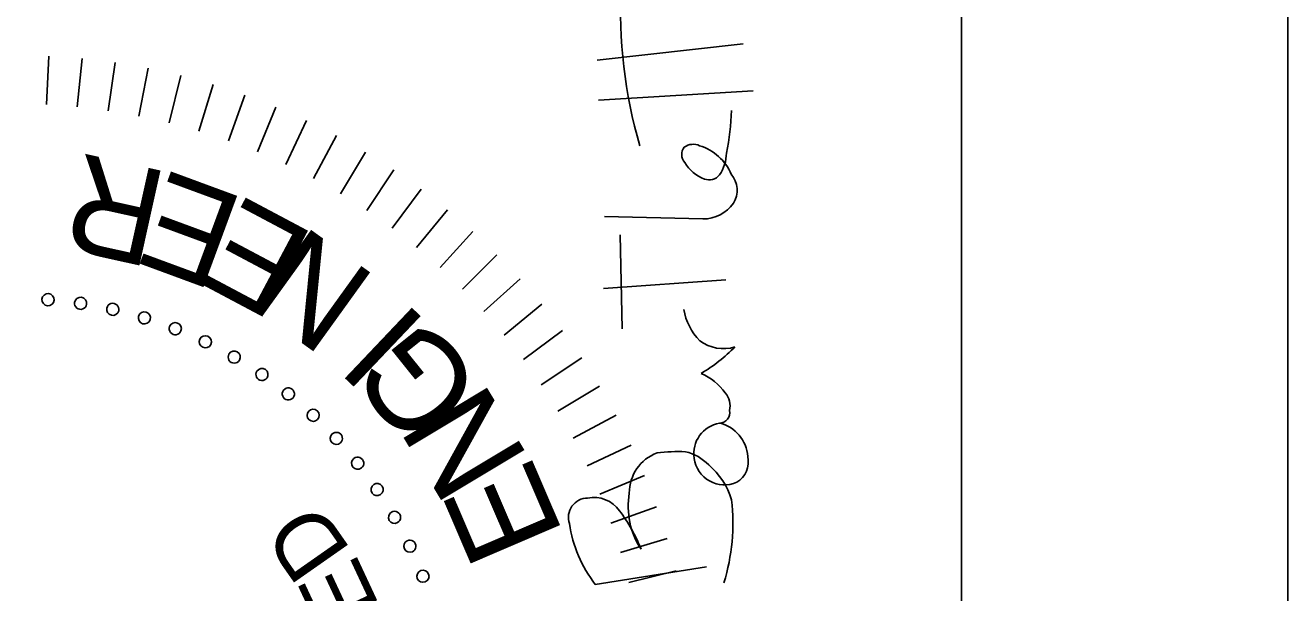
# Model space of a CAD drawing. Extents: x 916251 to 917164, y 328941 to 329491.
# Drawn here: x 917063.96 to 917100.87, y 329339.21 to 329355.8 of the extents above; entities that cross this region are included whole.
import ezdxf

# ---------------------------------------------------------------- set-up
doc = ezdxf.new("R2010")
doc.units = 0
for name, color, linetype in [('ANNOTATION', 7, 'Continuous'), ('Default', 7, 'Continuous'), ('elec-detail-ext-post-mtd-meter-panel', 7, 'Continuous')]:
    doc.layers.add(name, color=color, linetype=linetype)

# ---------------------------------------------------------------- blocks, each defined once
blk = doc.blocks.new('STAMP')
at = {"layer": 'Default'}
for p, q in [((0.007955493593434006, 0.0011091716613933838), (0.007387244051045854, 0.0011370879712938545)), ((0.007926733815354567, 0.0007192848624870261), (0.007360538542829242, 0.0007750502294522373)), ((0.007878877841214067, 0.00033127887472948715), (0.00731610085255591, 0.0004147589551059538)), ((0.007812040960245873, -5.3911561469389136e-05), (0.007254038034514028, 5.7082121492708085e-05)), ((0.007726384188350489, -0.0004353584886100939), (0.0071744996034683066, -0.00029711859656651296)), ((0.0076221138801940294, -0.0008121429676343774), (0.007077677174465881, -0.0006469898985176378)), ((0.007499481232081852, -0.0011833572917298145), (0.006963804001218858, -0.0009916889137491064)), ((0.007358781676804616, -0.0015481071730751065), (0.006833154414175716, -0.001330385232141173)), ((0.007200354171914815, -0.0019055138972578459), (0.006686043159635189, -0.0016622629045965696)), ((0.0070245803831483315, -0.0022547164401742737), (0.006522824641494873, -0.001986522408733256)), ((0.006831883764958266, -0.0025948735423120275), (0.006343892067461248, -0.002302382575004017)), ((0.006622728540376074, -0.002925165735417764), (0.006149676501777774, -0.0026090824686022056)), ((0.006397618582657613, -0.0032447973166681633), (0.005940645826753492, -0.0029058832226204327)), ((0.006157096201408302, -0.0035529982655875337), (0.005717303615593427, -0.0031920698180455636)), ((0.005901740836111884, -0.0038490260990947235), (0.005480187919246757, -0.0034669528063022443)), ((0.00563216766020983, -0.0041321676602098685), (0.0052298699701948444, -0.0037298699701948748)), ((0.005349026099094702, -0.004401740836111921), (0.004966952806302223, -0.003980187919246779)), ((0.005052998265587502, -0.004657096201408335), (0.004692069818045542, -0.004217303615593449)), ((0.004744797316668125, -0.0048976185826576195), (0.004405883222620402, -0.0044406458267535)), ((0.004425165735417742, -0.00512272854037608), (0.004109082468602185, -0.004649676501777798)), ((0.0040948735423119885, -0.005331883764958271), (0.003802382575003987, -0.004843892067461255)), ((0.0037547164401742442, -0.005524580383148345), (0.003486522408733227, -0.005022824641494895)), ((0.0034055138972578, -0.005700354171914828), (0.003162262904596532, -0.005186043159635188)), ((0.007905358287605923, -0.005303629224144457), (0.008096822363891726, -0.007011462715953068)), ((0.003048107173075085, -0.005858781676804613), (0.002830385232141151, -0.005333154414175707)), ((0.00523613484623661, -0.005376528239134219), (0.005338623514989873, -0.0068089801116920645)), ((0.007439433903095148, -0.005319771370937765), (0.0075498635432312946, -0.007129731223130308)), ((0.0023121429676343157, -0.006122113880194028), (0.0021469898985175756, -0.005577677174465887)), ((0.002683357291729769, -0.005999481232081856), (0.0024916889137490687, -0.005463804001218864)), ((0.004764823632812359, -0.005597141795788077), (0.005863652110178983, -0.005572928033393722)), ((0.0019353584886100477, -0.006226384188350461), (0.0017971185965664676, -0.005674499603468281))]:
    blk.add_line(p, q, dxfattribs=at)
for points in [[(0.0017747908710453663, -0.005281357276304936), (0.001982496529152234, -0.006583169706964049)], [(0.006077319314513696, -0.005389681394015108), (0.006050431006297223, -0.00653989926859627)]]:
    blk.add_lwpolyline(points, dxfattribs=at)
for centre, radius, start, end in [((0.005106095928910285, 0.0011173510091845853), 7.11168561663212e-05, 85.71428571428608, 265.71428571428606), ((0.005106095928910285, 0.0011173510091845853), 7.11168561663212e-05, 265.71428571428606, 85.71428571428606), ((0.005063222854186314, 0.0007368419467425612), 7.111685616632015e-05, 81.42857142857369, 261.4285714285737), ((0.005063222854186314, 0.0007368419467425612), 7.111685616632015e-05, 261.4285714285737, 81.42857142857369), ((0.004992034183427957, 0.00036060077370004), 7.111685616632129e-05, 77.14285714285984, 257.14285714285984), ((0.004992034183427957, 0.00036060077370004), 7.111685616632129e-05, 257.14285714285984, 77.14285714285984), ((0.004892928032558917, -9.268416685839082e-06), 7.111685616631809e-05, 72.85714285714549, 252.8571428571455), ((0.004892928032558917, -9.268416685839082e-06), 7.111685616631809e-05, 252.85714285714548, 72.85714285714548), ((0.0047664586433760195, -0.00037069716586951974), 7.111685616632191e-05, 68.57142857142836, 248.57142857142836), ((0.0047664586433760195, -0.00037069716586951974), 7.111685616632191e-05, 248.57142857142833, 68.57142857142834), ((0.0046133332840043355, -0.0007216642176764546), 7.111685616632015e-05, 64.28571428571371, 244.2857142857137), ((0.0046133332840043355, -0.0007216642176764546), 7.111685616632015e-05, 244.2857142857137, 64.2857142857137), ((0.00443440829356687, -0.0010602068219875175), 7.111685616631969e-05, 59.99999999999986, 239.99999999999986), ((0.00443440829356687, -0.0010602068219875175), 7.111685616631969e-05, 239.99999999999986, 59.99999999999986), ((0.004230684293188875, -0.0013844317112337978), 7.111685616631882e-05, 55.714285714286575, 235.71428571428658), ((0.004230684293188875, -0.0013844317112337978), 7.111685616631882e-05, 235.71428571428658, 55.714285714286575), ((0.004003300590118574, -0.0016925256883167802), 7.111685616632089e-05, 51.42857142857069, 231.4285714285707), ((0.004003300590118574, -0.0016925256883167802), 7.111685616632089e-05, 231.42857142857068, 51.42857142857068), ((0.003753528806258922, -0.0019827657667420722), 7.111685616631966e-05, 47.14285714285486, 227.14285714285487), ((0.003753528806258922, -0.0019827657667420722), 7.111685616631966e-05, 227.14285714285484, 47.14285714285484), ((0.0034827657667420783, -0.0022535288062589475), 7.111685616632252e-05, 42.857142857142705, 222.85714285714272), ((0.0034827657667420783, -0.0022535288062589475), 7.111685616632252e-05, 222.8571428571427, 42.85714285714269), ((0.0031925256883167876, -0.002503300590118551), 7.111685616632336e-05, 38.57142857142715, 218.57142857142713), ((0.0031925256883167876, -0.002503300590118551), 7.111685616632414e-05, 218.57142857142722, 38.57142857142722), ((0.002884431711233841, -0.0027306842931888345), 7.111685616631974e-05, 34.28571428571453, 214.28571428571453), ((0.002884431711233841, -0.0027306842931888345), 7.111685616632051e-05, 214.28571428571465, 34.28571428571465), ((0.0025602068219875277, -0.0029344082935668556), 7.111685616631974e-05, 30.000000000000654, 210.00000000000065), ((0.0025602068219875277, -0.002934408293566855), 7.111685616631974e-05, 210.00000000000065, 30.000000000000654), ((0.0022216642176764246, -0.0031133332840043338), 7.111685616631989e-05, 25.714285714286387, 205.71428571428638), ((0.0022216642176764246, -0.0031133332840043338), 7.111685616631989e-05, 205.71428571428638, 25.714285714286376), ((0.0018706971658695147, -0.0032664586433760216), 7.111685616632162e-05, 21.428571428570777, 201.42857142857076), ((0.0018706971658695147, -0.0032664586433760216), 7.111685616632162e-05, 201.42857142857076, 21.428571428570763), ((0.0027009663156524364, -0.006477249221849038), 0.001512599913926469, 98.17812986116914, 127.75649827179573), ((0.0025607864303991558, -0.005191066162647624), 0.0002239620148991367, 359.61429023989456, 109.56218572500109), ((0.0024288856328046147, -0.00526578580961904), 0.0003633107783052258, 304.8740098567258, 11.625468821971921), ((0.0015502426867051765, -0.00415818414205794), 0.0017765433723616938, 290.99837671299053, 307.69878588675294), ((0.008493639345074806, -0.011221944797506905), 0.00564567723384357, 87.11335107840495, 106.33073943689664), ((0.0026896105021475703, -0.006582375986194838), 0.0009159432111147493, 80.29637939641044, 123.29138431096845), ((0.0028457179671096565, -0.006179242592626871), 0.0004997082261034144, 20.58705533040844, 90.19763829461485), ((0.0014539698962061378, -0.006245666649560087), 0.0018752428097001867, 357.2040173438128, 7.418903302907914), ((0.0027994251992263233, -0.006216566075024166), 0.0005411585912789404, 313.71200852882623, 347.12598992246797), ((0.005109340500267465, -0.0069995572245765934), 0.000693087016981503, 99.83623703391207, 134.2279465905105), ((0.006942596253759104, -0.006719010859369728), 0.000455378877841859, 120.67649823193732, 159.39228314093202), ((0.006803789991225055, -0.00643536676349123), 0.00014287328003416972, 52.527438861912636, 130.8886473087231), ((0.00673895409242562, -0.006426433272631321), 0.0001842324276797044, 335.7048269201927, 34.54029227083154), ((0.0032953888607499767, -0.006791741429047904), 0.00035634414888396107, 97.37079091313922, 203.8922211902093), ((0.0033059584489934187, -0.006794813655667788), 0.0003608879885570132, 9.655140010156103, 98.97262191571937), ((0.002532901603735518, -0.0060711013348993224), 0.0008355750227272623, 286.05704557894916, 320.0421489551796), ((0.003588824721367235, -0.00621969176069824), 0.0007209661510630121, 306.1913846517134, 335.23134174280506), ((0.005998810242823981, -0.005456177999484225), 0.0020534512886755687, 211.2594929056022, 225.2513717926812), ((0.004994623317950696, -0.006780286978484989), 0.0004614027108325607, 143.047197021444, 196.91634387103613), ((0.006484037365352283, -0.0065437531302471), 0.0004336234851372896, 179.49077270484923, 234.71689370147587), ((0.006664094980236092, -0.006611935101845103), 0.00015702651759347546, 160.1953187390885, 230.79232729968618), ((0.006346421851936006, -0.006330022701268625), 0.0005863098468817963, 292.72445583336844, 342.91922299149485), ((0.0024869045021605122, -0.0045618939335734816), 0.0023287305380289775, 252.701645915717, 276.8342307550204), ((0.0032445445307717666, -0.006637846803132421), 0.00042819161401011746, 273.5716384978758, 346.98387133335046), ((0.0037841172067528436, -0.006733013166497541), 0.00012238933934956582, 180.59606692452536, 282.14231124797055), ((0.006821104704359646, -0.0063671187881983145), 0.0004472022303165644, 235.03647869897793, 269.9466508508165), ((0.003211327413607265, -0.006788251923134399), 0.0002833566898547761, 211.44349084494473, 282.2024112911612), ((0.0038601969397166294, -0.006618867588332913), 0.000239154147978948, 257.8497316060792, 310.1947013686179), ((0.006385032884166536, -0.006654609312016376), 0.00028643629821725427, 238.07646434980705, 310.98972037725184), ((0.007377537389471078, -0.004287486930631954), 0.0025874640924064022, 257.5721309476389, 268.73466328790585)]:
    blk.add_arc(centre, radius, start, end, dxfattribs=at)
for s, height, rotation, p in [('R', 0.001137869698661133, 77.5, (0.006589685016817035, -0.0003191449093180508)), ('E', 0.0011378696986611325, 69.75, (0.006276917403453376, -0.001210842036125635)), ('E', 0.0011378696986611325, 62, (0.005854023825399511, -0.002032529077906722)), ('N', 0.001137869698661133, 54.25000000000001, (0.005352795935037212, -0.0027499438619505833)), ('D', 0.0007680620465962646, 34.99999999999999, (0.002169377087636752, -0.0024365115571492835)), ('E', 0.0007680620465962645, 25.000000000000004, (0.001513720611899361, -0.002766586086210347)), ('I', 0.001137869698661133, 46.499999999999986, (0.004817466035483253, -0.003341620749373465)), ('G', 0.001137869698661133, 38.75000000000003, (0.004038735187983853, -0.004012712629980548)), ('N', 0.0011378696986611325, 30.999999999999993, (0.0032404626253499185, -0.004517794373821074)), ('E', 0.0011378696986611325, 23.249999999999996, (0.0023543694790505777, -0.004919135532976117))]:
    blk.add_text(s, height=height, rotation=rotation, dxfattribs=at).set_placement(p)

msp = doc.modelspace()

# ---------------------------------------------------------------- linework, layer by layer
at = {"layer": 'ANNOTATION'}
msp.add_lwpolyline([(916250.8701015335, 328941.0840016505), (917100.8684015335, 328941.0840016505), (917100.8684015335, 329491.0829016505), (916250.8701015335, 329491.0829016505)], close=True, dxfattribs=at)
at = {"layer": 'elec-detail-ext-post-mtd-meter-panel'}
msp.add_line((917091.3351521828, 328956.39453486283), (917091.3351521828, 329481.3934848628), dxfattribs=at)

# ---------------------------------------------------------------- block references
at = {"layer": 'elec-detail-ext-post-mtd-meter-panel', "xscale": 2499.999999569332, "yscale": 2499.999999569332, "rotation": 90}
msp.add_blockref('STAMP', (917067.4209062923, 329335.01261332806), dxfattribs=at)

doc.saveas('drawing.dxf')
